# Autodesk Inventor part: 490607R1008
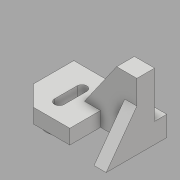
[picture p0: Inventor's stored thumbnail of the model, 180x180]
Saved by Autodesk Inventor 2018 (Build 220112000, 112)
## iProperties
Created: 2019-06
Part Number: 490607R1008
Material: 일반
Document SubType Name: Modeling
Designer: 6507_06
Density: 1 g/cm^3
Appearance: 기본값
Author: 6507_06
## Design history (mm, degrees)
sketch "스케치1"
  geometry: L1 (-10, -37.5)-(-35, -12.5); L2 (-35, -12.5)-(-35, 37.5); L3 (-10, -37.5)-(35, -37.5); L4 (35, -37.5)-(35, 37.5); L5 (35, 37.5)-(-35, 37.5); 1 further point
  constraints: 10 end point, 2 perpendicular, 1 horizontal, 1 vertical
  dimensions: "d0" = 70 distance between parallel lines of L4 L2; "d1" = 35 distance from line of point (0, 0) L2; "d2" = 75 distance between parallel lines of L3 L5; "d3" = 25 horizontal distance of L1.start L1.end; "d4" = 45 deg angle of L3 L1; "d5" = 37.5 distance from line of point (0, 0) L5
extrude "돌출1" new body sketch "스케치1" stored distance "d6" = 18; taper "d7" = 0 deg
sketch "스케치3"
  geometry: L1 (-35, -12.5)-(-35, 37.5) reference; L2 (-6, 12.5)-(-6, -15.5); L3 (6, 12.5)-(6, -15.5); L4 (-35, 37.5)-(35, 37.5) reference; A1 r 6 centre (0, 12.5) between (6, 12.5) and (-6, 12.5); A2 r 6 centre (0, -15.5) between (-6, -15.5) and (6, -15.5); 1 further point
  constraints: 4 end point, 4 point on circle, 2 centre point, 2 tangent, 1 parallel, 1 vertical, 1 vertical alignment
  dimensions: "d8" = 12 diameter of A1; "d9" = 12 diameter of A2; "d10" = 35 distance from line of A1.centre L1; "d11" = 28 distance of A2.centre A1.centre; "d12" = 53 distance from line of L4 A2.centre
extrude "돌출2" cut sketch "스케치3" distance "d13" = 12; taper "d14" = 0 deg
sketch "스케치4"
  geometry: C1 r 16 at (0, -15.5); C2 r 10 at (0, -15.5); A1 r 6 centre (0, -15.5) between (-6, -15.5) and (6, -15.5) reference; 1 further point
  constraints: 2 centre point, 2 coincident
  dimensions: "d15" = 32 diameter of C1; "d16" = 20 diameter of C2
extrude "돌출3" join sketch "스케치4" distance "d17" = 7; taper "d18" = 0 deg
sketch "스케치5"
  geometry: L1 (0, 75)-(0, 25) reference; L2 (18, 75)-(0, 75); L3 (0, 75)-(0, 60); L4 (0, 60)-(18, 60); L5 (18, 60)-(18, 75); 1 further point
  constraints: 8 end point, 2 parallel, 1 horizontal, 1 perpendicular, 1 point on line
  dimensions: "d19" = 15 distance between parallel lines of L2 L4
extrude "돌출4" join sketch "스케치5" distance "d20" = 45; taper "d21" = 0 deg
sketch "스케치7"
  geometry: L1 (-70, 18)-(45, 18) reference; L2 (-70, 0)-(45, 0) reference; L3 (45, 0)-(45, 75); L4 (45, 75)-(20, 75); L5 (20, 75)-(-19.912, 18); L6 (-19.912, 18)-(0, 18); L7 (45, 0)-(0, 0); L8 (0, 18)-(0, 0) reference; L9 (0, 18)-(0, 0); 1 further point
  constraints: 12 end point, 2 point on line, 1 collinear, 1 horizontal, 1 perpendicular, 1 vertical
  dimensions: "d22" = 75 distance of L2.end L3.end; "d23" = 25 distance of L3.end L4.end; "d24" = 55 deg angle of L4 L5
extrude "돌출5" join sketch "스케치7" distance "d25" = 22; taper "d26" = 0 deg
sketch "스케치8"
  geometry: L1 (-57, 38)-(0, 38) reference; L2 (-27.303, 38)-(25, 0); L3 (25, 0)-(25, 38); L4 (25, 6)-(25, 38) reference; L5 (-27.303, 38)-(25, 38); L6 (18, 38)-(0, 38) reference; 1 further point
  constraints: 6 end point, 2 collinear, 2 point on line, 1 coincident
  dimensions: "d33" = 144 deg angle of L1 L2; "d35" = 38 distance from line of L5 L2.end
extrude "돌출6" join sketch "스케치8" distance "d29" = 15; taper "d30" = 0 deg
sketch "스케치9"
  geometry: L1 (18, 38)-(25, 38) reference; L2 (18, 38)-(25, 38); L3 (25, 38)-(25, 75); L4 (25, 75)-(18, 75); L5 (18, 75)-(18, 38); L6 (25, 38)-(25, 0) reference; L7 (0, 75)-(18, 75) reference; 2 further points
  constraints: 8 end point, 2 parallel, 1 collinear, 1 horizontal, 1 midpoint, 1 perpendicular
extrude "돌출7" join sketch "스케치9" distance "d36" = 15; taper "d37" = 0 deg
node "솔리드1"
